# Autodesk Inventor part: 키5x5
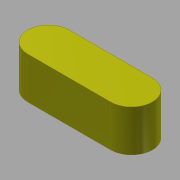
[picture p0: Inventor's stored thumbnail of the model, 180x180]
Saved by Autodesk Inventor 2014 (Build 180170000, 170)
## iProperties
Created: 2011-04
Part Number: 키5x5
Document SubType Name: Modeling
Designer: pww
Density: 7.86 g/cm^3
Material: 강철, 연강
Appearance: 노란색
Author: pww
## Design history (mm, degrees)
sketch "스케치1"
  geometry: L1 (-5, -2.5)-(5, -2.5); L2 (5, 2.5)-(-5, 2.5); A1 r 2.5 centre (-5, 0) between (-5, 2.5) and (-5, -2.5); A2 r 2.5 centre (5, 0) between (5, -2.5) and (5, 2.5); 1 further point
  constraints: 4 end point, 4 point on circle, 2 centre point
extrude "돌출1" new body sketch "스케치1" distance "d0" = 5; taper "d1" = 0 deg
node "솔리드1"
